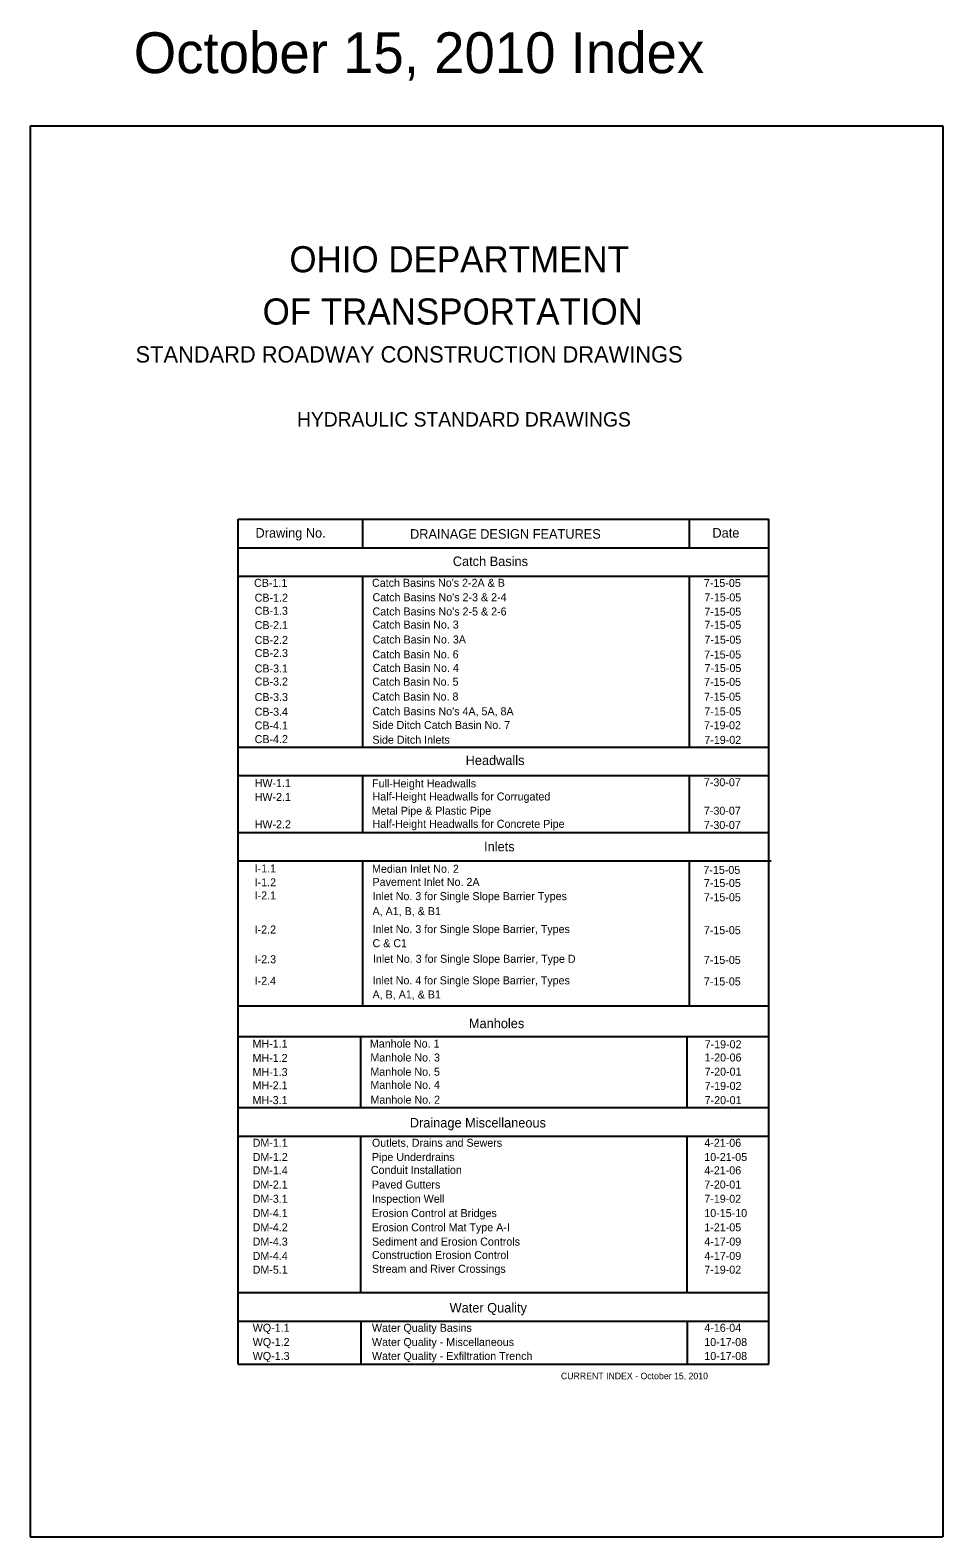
# Model space of a CAD drawing. Extents: x 146 to 619, y 56 to 2134.
# Drawn here: x 597.17 to 619.17, y 2097.9 to 2134.21 of the extents above; entities that cross this region are included whole.
import ezdxf

# ---------------------------------------------------------------- set-up
doc = ezdxf.new("R2010")
doc.units = 0
doc.layers.add('Level 1', color=7, linetype='Continuous')

msp = doc.modelspace()

# ---------------------------------------------------------------- linework, layer by layer
at = {"layer": 'Level 1'}
for p, q in [((597.168, 2131.9), (619.168, 2131.9)), ((597.168, 2131.9), (597.168, 2097.9)), ((619.168, 2131.9), (619.168, 2097.9)), ((602.185, 2102.061), (602.185, 2122.419)), ((602.185, 2122.419), (614.974, 2122.419)), ((602.185, 2122.419), (602.185, 2122.419)), ((605.188, 2121.733), (605.188, 2122.419)), ((613.058, 2121.733), (613.058, 2122.419)), ((614.974, 2102.061), (614.974, 2122.419)), ((614.974, 2122.419), (614.974, 2122.419)), ((602.185, 2121.733), (614.974, 2121.733)), ((602.185, 2121.047), (614.974, 2121.047)), ((605.188, 2116.932), (605.188, 2121.047)), ((613.058, 2116.932), (613.058, 2121.047)), ((602.185, 2116.932), (614.974, 2116.932)), ((602.185, 2116.246), (614.974, 2116.246)), ((605.188, 2114.872), (605.188, 2116.246)), ((613.058, 2114.872), (613.058, 2116.246)), ((602.185, 2114.874), (614.974, 2114.874)), ((602.185, 2114.188), (614.974, 2114.188)), ((602.237, 2114.188), (615.026, 2114.188)), ((605.188, 2114.188), (605.188, 2114.192)), ((605.188, 2110.695), (605.188, 2114.188)), ((613.058, 2114.188), (613.058, 2114.189)), ((613.058, 2110.695), (613.058, 2114.188)), ((602.185, 2110.695), (614.974, 2110.695)), ((602.185, 2109.958), (614.974, 2109.958)), ((605.137, 2108.243), (605.137, 2109.958)), ((613.007, 2108.266), (613.007, 2109.958)), ((605.137, 2108.243), (605.137, 2109.272)), ((613.007, 2108.243), (613.007, 2109.272)), ((602.185, 2108.243), (614.974, 2108.243)), ((602.185, 2107.557), (614.974, 2107.557)), ((605.137, 2106.554), (605.137, 2107.557)), ((613.007, 2106.554), (613.007, 2107.557)), ((613.007, 2105.195), (613.007, 2107.536)), ((605.137, 2104.652), (605.137, 2107.027)), ((605.137, 2103.785), (605.137, 2105.525)), ((613.007, 2103.785), (613.007, 2105.546)), ((602.185, 2103.785), (614.974, 2103.785)), ((602.185, 2103.099), (614.974, 2103.099)), ((605.137, 2103.099), (605.137, 2102.061)), ((613.007, 2103.098), (613.007, 2102.062)), ((602.185, 2102.061), (614.974, 2102.061)), ((597.168, 2097.9), (619.168, 2097.9))]:
    msp.add_line(p, q, dxfattribs=at)

# ---------------------------------------------------------------- texts
for s, height, p in [('October 15, 2010 Index', 0.98375, (599.666, 2133.169)), ('OHIO DEPARTMENT', 0.6296, (603.417, 2128.37)), ('OF TRANSPORTATION', 0.6296, (602.772, 2127.111)), ('STANDARD ROADWAY CONSTRUCTION DRAWINGS', 0.3935, (599.71, 2126.196)), ('HYDRAULIC STANDARD DRAWINGS', 0.34707, (603.601, 2124.653)), ('Drawing No.', 0.23, (602.6, 2121.977)), ('DRAINAGE DESIGN FEATURES', 0.23, (606.325, 2121.951)), ('Date', 0.23, (613.614, 2121.977)), ('Catch Basins', 0.23, (607.356, 2121.292)), ('CB-1.1', 0.1928, (602.566, 2120.791)), ("Catch Basins No's 2-2A & B", 0.1928, (605.409, 2120.792)), ('7-15-05', 0.1928, (613.408, 2120.788)), ('CB-1.2', 0.1928, (602.58, 2120.433)), ("Catch Basins No's 2-3 & 2-4", 0.1928, (605.421, 2120.444)), ('7-15-05', 0.1928, (613.419, 2120.44)), ('CB-1.3', 0.1928, (602.58, 2120.118)), ("Catch Basins No's 2-5 & 2-6", 0.1928, (605.421, 2120.101)), ('7-15-05', 0.1928, (613.419, 2120.097)), ('CB-2.1', 0.1928, (602.58, 2119.774)), ('Catch Basin No. 3', 0.1928, (605.421, 2119.785)), ('7-15-05', 0.1928, (613.419, 2119.78)), ('CB-2.2', 0.1928, (602.58, 2119.416)), ('Catch Basin No. 3A', 0.1928, (605.423, 2119.426)), ('7-15-05', 0.1928, (613.421, 2119.422)), ('CB-2.3', 0.1928, (602.58, 2119.1)), ('Catch Basin No. 6', 0.1928, (605.418, 2119.068)), ('7-15-05', 0.1928, (613.416, 2119.064)), ('CB-3.1', 0.1928, (602.58, 2118.728)), ('Catch Basin No. 4', 0.1928, (605.424, 2118.742)), ('7-15-05', 0.1928, (613.422, 2118.738)), ('CB-3.2', 0.1928, (602.58, 2118.413)), ('Catch Basin No. 5', 0.1928, (605.415, 2118.409)), ('7-15-05', 0.1928, (613.414, 2118.405)), ('CB-3.3', 0.1928, (602.58, 2118.04)), ('Catch Basin No. 8', 0.1928, (605.414, 2118.051)), ('7-15-05', 0.1928, (613.412, 2118.047)), ('CB-3.4', 0.1928, (602.58, 2117.686)), ("Catch Basins No's 4A, 5A, 8A", 0.1928, (605.419, 2117.697)), ('7-15-05', 0.1928, (613.418, 2117.693)), ('CB-4.1', 0.1928, (602.58, 2117.354)), ('Side Ditch Catch Basin No. 7', 0.1928, (605.414, 2117.366)), ('7-19-02', 0.1928, (613.412, 2117.361)), ('CB-4.2', 0.1928, (602.58, 2117.025)), ('Side Ditch Inlets', 0.1928, (605.419, 2117.011)), ('7-19-02', 0.1928, (613.418, 2117.007)), ('Headwalls', 0.23, (607.665, 2116.497)), ('HW-1.1', 0.1928, (602.58, 2115.967)), ('Full-Height Headwalls', 0.1928, (605.409, 2115.959)), ('7-30-07', 0.1928, (613.408, 2115.986)), ('HW-2.1', 0.1928, (602.58, 2115.632)), ('Half-Height Headwalls for Corrugated ', 0.1928, (605.421, 2115.643)), ('       Metal Pipe & Plastic Pipe', 0.1928, (604.898, 2115.3)), ('Half-Height Headwalls for Concrete Pipe', 0.1928, (605.421, 2114.984)), ('7-30-07', 0.1928, (613.408, 2115.3)), ('HW-2.2', 0.1928, (602.58, 2114.974)), ('7-30-07', 0.1928, (613.408, 2114.957)), ('Inlets', 0.23, (608.11, 2114.418)), ('I-1.1', 0.1928, (602.58, 2113.91)), ('Median Inlet No. 2', 0.1928, (605.409, 2113.901)), ('I-1.2', 0.1928, (602.58, 2113.574)), ('Pavement Inlet No. 2A', 0.1928, (605.421, 2113.585)), ('7-15-05', 0.1928, (613.396, 2113.874)), ('7-15-05', 0.1928, (613.408, 2113.558)), ('I-2.1', 0.1928, (602.58, 2113.259)), ('Inlet No. 3 for Single Slope Barrier Types ', 0.1928, (605.421, 2113.242)), ('7-15-05', 0.1928, (613.408, 2113.215)), ('A, A1, B, & B1', 0.1928, (605.421, 2112.881)), ('I-2.2', 0.1928, (602.58, 2112.438)), ('Inlet No. 3 for Single Slope Barrier, Types', 0.1928, (605.421, 2112.449)), ('C & C1', 0.1928, (605.421, 2112.108)), ('7-15-05', 0.1928, (613.407, 2112.422)), ('I-2.3', 0.1928, (602.58, 2111.721)), ('Inlet No. 3 for Single Slope Barrier, Type D', 0.1928, (605.429, 2111.732)), ('7-15-05', 0.1928, (613.407, 2111.705)), ('I-2.4', 0.1928, (602.58, 2111.202)), ('Inlet No. 4 for Single Slope Barrier, Types', 0.1928, (605.421, 2111.213)), ('7-15-05', 0.1928, (613.407, 2111.186)), ('A, B, A1, & B1', 0.1928, (605.421, 2110.872)), ('Manholes', 0.23, (607.744, 2110.158)), ('MH-1.1', 0.1928, (602.528, 2109.687)), ('Manhole No. 1', 0.1928, (605.358, 2109.69)), ('7-19-02', 0.1928, (613.426, 2109.672)), ('MH-1.2', 0.1928, (602.528, 2109.343)), ('Manhole No. 3', 0.1928, (605.369, 2109.354)), ('1-20-06', 0.1928, (613.426, 2109.355)), ('MH-1.3', 0.1928, (602.528, 2109.003)), ('Manhole No. 5', 0.1928, (605.369, 2109.011)), ('7-20-01', 0.1928, (613.426, 2109.012)), ('MH-2.1', 0.1928, (602.528, 2108.684)), ('Manhole No. 4', 0.1928, (605.369, 2108.695)), ('7-19-02', 0.1928, (613.426, 2108.669)), ('MH-3.1', 0.1928, (602.528, 2108.326)), ('Manhole No. 2', 0.1928, (605.371, 2108.337)), ('7-20-01', 0.1928, (613.426, 2108.326)), ('Drainage Miscellaneous', 0.23, (606.319, 2107.764)), ('DM-1.1', 0.1928, (602.532, 2107.299)), ('Outlets, Drains and Sewers', 0.1928, (605.407, 2107.299)), ('4-21-06', 0.1928, (613.418, 2107.299)), ('DM-1.2', 0.1928, (602.532, 2106.956)), ('DM-1.4', 0.1928, (602.532, 2106.635)), ('Conduit Installation', 0.1928, (605.381, 2106.645)), ('Pipe Underdrains', 0.1928, (605.407, 2106.956)), ('4-21-06', 0.1928, (613.418, 2106.635)), ('10-21-05', 0.1928, (613.418, 2106.956)), ('7-19-02', 0.1928, (613.418, 2105.95)), ('10-15-10', 0.1928, (613.418, 2105.605)), ('1-21-05', 0.1928, (613.418, 2105.262)), ('4-17-09', 0.1928, (613.418, 2104.918)), ('4-17-09', 0.1928, (613.418, 2104.573)), ('7-19-02', 0.1928, (613.418, 2104.242)), ('Water Quality', 0.23, (607.279, 2103.306)), ('WQ-1.1', 0.1928, (602.533, 2102.841)), ('Water Quality Basins', 0.1928, (605.407, 2102.841)), ('4-16-04', 0.1928, (613.418, 2102.841)), ('WQ-1.2', 0.1928, (602.533, 2102.498)), ('Water Quality - Miscellaneous', 0.1928, (605.407, 2102.498)), ('10-17-08', 0.1928, (613.418, 2102.498)), ('WQ-1.3', 0.1928, (602.533, 2102.162)), ('Water Quality - Exfiltration Trench', 0.1928, (605.407, 2102.162)), ('10-17-08', 0.1928, (613.418, 2102.162)), ('CURRENT INDEX - October 15, 2010', 0.1574, (609.962, 2101.698))]:
    msp.add_text(s, height=height, dxfattribs=at).set_placement(p)
for s, p in [('DM-2.1', (602.532, 2106.293)), ('Paved Gutters', (605.407, 2106.293)), ('7-20-01', (613.418, 2106.293)), ('DM-3.1', (602.532, 2105.95)), ('Inspection Well', (605.407, 2105.95)), ('DM-4.1', (602.532, 2105.605)), ('Erosion Control at Bridges', (605.407, 2105.605)), ('DM-4.2', (602.532, 2105.262)), ('Erosion Control Mat Type A-I', (605.407, 2105.262)), ('DM-4.3', (602.532, 2104.918)), ('Sediment and Erosion Controls', (605.407, 2104.918)), ('DM-4.4', (602.532, 2104.573)), ('Construction Erosion Control', (605.407, 2104.596)), ('DM-5.1', (602.532, 2104.242)), ('Stream and River Crossings', (605.407, 2104.263))]:
    msp.add_text(s, height=0.1928, rotation=360, dxfattribs=at).set_placement(p)

doc.saveas('drawing.dxf')
